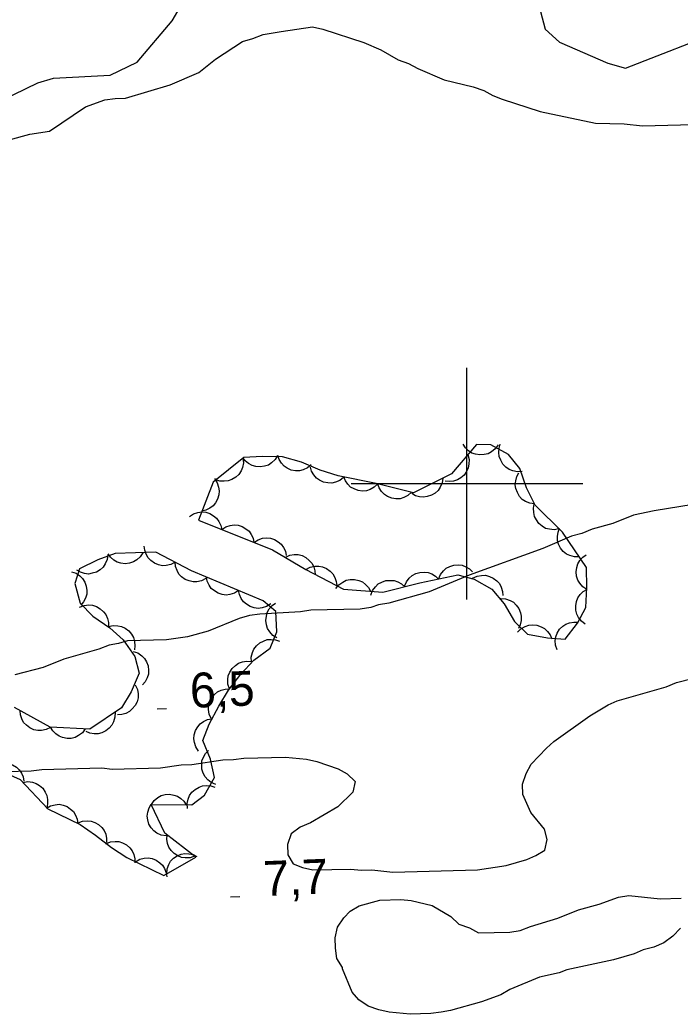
# Model space of a CAD drawing. Extents: x 336540 to 340074, y 5572036 to 5573747.
# Drawn here: x 337361.4 to 337418.4, y 5572954.2 to 5573040 of the extents above; entities that cross this region are included whole.
import ezdxf

# ---------------------------------------------------------------- set-up
doc = ezdxf.new("R2010")
doc.units = 0
for name, color, linetype in [('Niveau 2', 7, 'Continuous'), ('Niveau 3', 7, 'Continuous'), ('Niveau 44', 7, 'Continuous'), ('Niveau 61', 7, 'Continuous')]:
    doc.layers.add(name, color=color, linetype=linetype)

msp = doc.modelspace()

# ---------------------------------------------------------------- linework, layer by layer
at = {"layer": 'Niveau 2'}
for points in [[(337311.92, 5573027.2), (337321.42, 5573026.84), (337323.62, 5573026.6), (337325.18, 5573025.85), (337328.23, 5573022.94), (337330.16, 5573021.51), (337331.52, 5573021.09), (337334.91, 5573021.09), (337337.1, 5573021.71), (337339.82, 5573024.41), (337343.42, 5573026.96), (337351.15, 5573031.07), (337354.47, 5573032.27), (337359.85, 5573033.05), (337362.98, 5573034.59), (337364.33, 5573034.99), (337369.22, 5573035.24), (337371.54, 5573036.37), (337374.57, 5573039.93), (337377.21, 5573044.47)], [(337406.35, 5573040.72), (337406.74, 5573039.21), (337407.99, 5573038.09), (337412.15, 5573036.27), (337413.69, 5573035.83), (337422.39, 5573039.25), (337426.4, 5573040.99)], [(337360.5, 5573029.65), (337362.29, 5573030.14), (337363.98, 5573030.4), (337367.09, 5573032.5), (337368.76, 5573033.1), (337369.66, 5573033.23), (337370.56, 5573033.25), (337374.41, 5573034.4), (337376.86, 5573035.47), (337378.3, 5573036.63), (337380.63, 5573038.15), (337381.52, 5573038.4), (337382.41, 5573038.76), (337383.98, 5573039.02), (337386.68, 5573039.42), (337387.58, 5573039.22), (337391.1, 5573038.06), (337392.58, 5573037.42), (337394.06, 5573036.56), (337394.97, 5573036.24), (337395.77, 5573035.81), (337398.05, 5573034.85), (337400.54, 5573034.23), (337401.45, 5573033.92), (337402.24, 5573033.48), (337403.04, 5573033.17), (337406.33, 5573032.12), (337411.08, 5573031.1), (337413.56, 5573031.05), (337415.14, 5573030.86), (337419.53, 5573030.97)], [(337419.52, 5572998.19), (337416.16, 5572997.66), (337414.37, 5572997.28), (337412.58, 5572996.56), (337410.79, 5572996.07), (337409.9, 5572995.71), (337409.01, 5572995.46), (337406.55, 5572994.39), (337400.19, 5572992.1), (337396.74, 5572990.67), (337393.27, 5572989.68), (337392.37, 5572989.55), (337391.7, 5572989.31), (337390.8, 5572989.17), (337386.53, 5572989.07), (337385.63, 5572988.94), (337382.14, 5572988.74), (337381.25, 5572988.61), (337380.35, 5572988.36), (337377.67, 5572987.28), (337375.88, 5572986.79), (337374.09, 5572986.52), (337370.71, 5572986.44), (337369.93, 5572986.2)], [(337369.93, 5572986.2), (337369.15, 5572986.07), (337368.25, 5572985.71), (337365.23, 5572984.85), (337363.45, 5572984.13), (337360.99, 5572983.51)], [(337412.95, 5572981.26), (337417.2, 5572982.48), (337418.09, 5572982.84), (337421, 5572983.59)], [(337359.05, 5572975.13), (337362.42, 5572975.21), (337363.32, 5572975.34), (337368.5, 5572975.47), (337369.4, 5572975.37), (337373.57, 5572975.47), (337375.36, 5572975.74), (337376.26, 5572975.76), (337378.95, 5572976.17), (337379.85, 5572976.19), (337380.75, 5572976.32), (337384.35, 5572976.41), (337386.16, 5572976.22), (337387.06, 5572976.02), (337388.88, 5572975.39), (337389.68, 5572974.96), (337390.37, 5572974.3), (337390.17, 5572973.39), (337388.85, 5572972.12), (337386.51, 5572970.72), (337385.62, 5572970.36), (337384.85, 5572969.77), (337384.53, 5572968.87), (337384.55, 5572967.97), (337385.02, 5572967.19), (337385.82, 5572966.87), (337386.72, 5572966.67), (337389.99, 5572966.74), (337390.89, 5572966.65), (337391.79, 5572966.67), (337393.6, 5572966.49), (337400.91, 5572966.67), (337403.38, 5572967.06), (337405.17, 5572967.56), (337405.95, 5572967.91), (337406.72, 5572968.38), (337406.93, 5572969.29), (337406.68, 5572970.18), (337405.52, 5572971.62), (337404.81, 5572973.18), (337404.79, 5572974.08), (337405.1, 5572974.99), (337405.53, 5572975.79), (337406.85, 5572977.17), (337407.51, 5572977.75), (337410.61, 5572979.96), (337412.17, 5572980.9), (337412.95, 5572981.26)], [(337389.26, 5572958.14), (337389.26, 5572958.25), (337388.79, 5572959.03), (337388.66, 5572959.92), (337388.64, 5572960.82), (337388.84, 5572961.73), (337389.38, 5572962.53), (337389.93, 5572963.11), (337390.71, 5572963.57), (337392.5, 5572964.07), (337394.3, 5572964.11), (337395.2, 5572964.02), (337397.01, 5572963.61), (337398.61, 5572962.64), (337399.3, 5572961.98), (337400.21, 5572961.66), (337401, 5572961.23), (337403.7, 5572961.3), (337404.6, 5572961.43), (337405.49, 5572961.79), (337407.83, 5572962.52), (337409.62, 5572963.24), (337411.41, 5572963.73), (337413.08, 5572964.33), (337413.98, 5572964.47), (337416.68, 5572964.19), (337418.48, 5572964.24)], [(337418.43, 5572961.65), (337417.77, 5572960.96), (337417, 5572960.38), (337416.11, 5572960.02), (337415.21, 5572959.77), (337414.43, 5572959.42), (337412.65, 5572958.92), (337408.62, 5572958.04), (337407.95, 5572957.8), (337406.27, 5572957.42), (337403.71, 5572956.35), (337402.93, 5572955.88), (337401.26, 5572955.28), (337398.58, 5572954.54), (337397.79, 5572954.4), (337396.89, 5572954.27), (337395.1, 5572954.23), (337393.29, 5572954.41), (337392.39, 5572954.61), (337391.48, 5572954.93), (337390.68, 5572955.47), (337390.1, 5572956.13), (337389.26, 5572958.14)]]:
    msp.add_lwpolyline(points, dxfattribs=at)
at = {"layer": 'Niveau 3'}
for p, q in [((337373.28, 5572980.58), (337374.08, 5572980.61)), ((337379.61, 5572964.34), (337380.41, 5572964.38))]:
    msp.add_line(p, q, dxfattribs=at)
at = {"layer": 'Niveau 44'}
for points in [[(337386.11, 5572992.59), (337389.35, 5572990.9), (337392.74, 5572990.64), (337395.95, 5572991.43), (337399.21, 5572992.12), (337400.63, 5572991.75), (337402.14, 5572990.89), (337403.2, 5572989.62), (337404.09, 5572988.1), (337405.23, 5572987.02), (337406.95, 5572986.69), (337408.47, 5572986.58), (337409.53, 5572987.97), (337410.27, 5572989.3), (337410.35, 5572991.05), (337410.31, 5572992.76), (337408.23, 5572995.8), (337405.89, 5572998.15), (337405.13, 5572999.65), (337404.56, 5573001.31), (337403.6, 5573002.5), (337402.07, 5573003.35), (337400.83, 5573003.37), (337398.66, 5573000.85), (337395.38, 5572999.21), (337392.16, 5573000), (337388.9, 5573000.68), (337387.34, 5573001.16), (337385.73, 5573001.85), (337384.09, 5573002.31), (337382.34, 5573002.35), (337380.74, 5573002.26), (337378.1, 5573000.13), (337376.83, 5572996.86), (337383.23, 5572994.28), (337386.11, 5572992.59)], [(337402.68, 5573003.34), (337402.44, 5573003), (337402.12, 5573002.75), (337401.83, 5573002.58), (337401.49, 5573002.5), (337401.12, 5573002.47), (337400.75, 5573002.54), (337400.43, 5573002.63), (337400.14, 5573002.83), (337399.87, 5573003.09), (337399.68, 5573003.39)], [(337404.77, 5573001.06), (337404.35, 5573001.02), (337403.95, 5573001.11), (337403.64, 5573001.22), (337403.36, 5573001.42), (337403.1, 5573001.69), (337402.91, 5573002.03), (337402.79, 5573002.33), (337402.75, 5573002.68), (337402.78, 5573003.05), (337402.88, 5573003.39)], [(337383.66, 5573002.42), (337383.45, 5573002.07), (337383.15, 5573001.79), (337382.87, 5573001.6), (337382.54, 5573001.5), (337382.17, 5573001.44), (337381.79, 5573001.49), (337381.47, 5573001.56), (337381.17, 5573001.73), (337380.88, 5573001.97), (337380.67, 5573002.26)], [(337386.57, 5573001.62), (337386.25, 5573001.35), (337385.87, 5573001.18), (337385.56, 5573001.09), (337385.21, 5573001.1), (337384.84, 5573001.17), (337384.5, 5573001.33), (337384.22, 5573001.5), (337383.99, 5573001.77), (337383.79, 5573002.08), (337383.68, 5573002.43)], [(337400.08, 5573002.5), (337400.19, 5573002.09), (337400.17, 5573001.69), (337400.12, 5573001.36), (337399.97, 5573001.04), (337399.75, 5573000.74), (337399.46, 5573000.5), (337399.18, 5573000.32), (337398.85, 5573000.22), (337398.48, 5573000.18), (337398.12, 5573000.22)], [(337380.68, 5573002.21), (337380.72, 5573001.8), (337380.63, 5573001.4), (337380.52, 5573001.09), (337380.31, 5573000.8), (337380.05, 5573000.55), (337379.71, 5573000.36), (337379.41, 5573000.23), (337379.06, 5573000.2), (337378.69, 5573000.22), (337378.35, 5573000.33)], [(337389.36, 5573000.54), (337389.04, 5573000.28), (337388.66, 5573000.12), (337388.34, 5573000.04), (337387.99, 5573000.06), (337387.63, 5573000.13), (337387.29, 5573000.31), (337387.01, 5573000.48), (337386.79, 5573000.75), (337386.6, 5573001.08), (337386.5, 5573001.42)], [(337392.31, 5572999.97), (337392.01, 5572999.68), (337391.65, 5572999.49), (337391.34, 5572999.38), (337390.99, 5572999.36), (337390.62, 5572999.41), (337390.26, 5572999.55), (337389.97, 5572999.7), (337389.73, 5572999.95), (337389.51, 5573000.25), (337389.38, 5573000.58)], [(337405.84, 5572998.25), (337405.43, 5572998.3), (337405.06, 5572998.47), (337404.77, 5572998.64), (337404.54, 5572998.9), (337404.35, 5572999.22), (337404.23, 5572999.58), (337404.17, 5572999.9), (337404.21, 5573000.25), (337404.31, 5573000.61), (337404.48, 5573000.92)], [(337378.21, 5573000.43), (337378.45, 5573000.08), (337378.58, 5572999.7), (337378.64, 5572999.37), (337378.6, 5572999.02), (337378.49, 5572998.67), (337378.3, 5572998.34), (337378.1, 5572998.08), (337377.81, 5572997.87), (337377.48, 5572997.71), (337377.13, 5572997.63)], [(337395.22, 5572999.25), (337394.91, 5572998.97), (337394.55, 5572998.79), (337394.23, 5572998.69), (337393.88, 5572998.69), (337393.52, 5572998.74), (337393.16, 5572998.9), (337392.88, 5572999.06), (337392.64, 5572999.32), (337392.44, 5572999.63), (337392.31, 5572999.96)], [(337397.92, 5573000.48), (337397.87, 5573000.07), (337397.7, 5572999.7), (337397.52, 5572999.42), (337397.26, 5572999.18), (337396.94, 5572998.99), (337396.58, 5572998.88), (337396.26, 5572998.82), (337395.91, 5572998.86), (337395.55, 5572998.96), (337395.24, 5572999.14)], [(337407.93, 5572996.1), (337407.52, 5572996.02), (337407.12, 5572996.07), (337406.79, 5572996.14), (337406.49, 5572996.32), (337406.21, 5572996.56), (337405.99, 5572996.87), (337405.83, 5572997.16), (337405.76, 5572997.5), (337405.74, 5572997.87), (337405.81, 5572998.23)], [(337376.06, 5572997.17), (337376.41, 5572997.4), (337376.8, 5572997.52), (337377.13, 5572997.58), (337377.47, 5572997.53), (337377.83, 5572997.42), (337378.15, 5572997.22), (337378.41, 5572997.02), (337378.61, 5572996.73), (337378.77, 5572996.4), (337378.85, 5572996.05)], [(337378.85, 5572996.05), (337379.19, 5572996.28), (337379.58, 5572996.4), (337379.91, 5572996.45), (337380.26, 5572996.41), (337380.61, 5572996.3), (337380.94, 5572996.1), (337381.2, 5572995.9), (337381.4, 5572995.61), (337381.55, 5572995.28), (337381.63, 5572994.93)], [(337409.68, 5572993.68), (337409.27, 5572993.67), (337408.88, 5572993.79), (337408.58, 5572993.92), (337408.31, 5572994.15), (337408.07, 5572994.44), (337407.91, 5572994.79), (337407.81, 5572995.1), (337407.8, 5572995.45), (337407.86, 5572995.82), (337407.99, 5572996.15)], [(337374.82, 5572993.21), (337374.45, 5572993.02), (337374.06, 5572992.94), (337373.73, 5572992.91), (337373.38, 5572992.99), (337373.04, 5572993.13), (337372.74, 5572993.37), (337372.5, 5572993.59), (337372.33, 5572993.9), (337372.21, 5572994.25), (337372.17, 5572994.61)], [(337381.63, 5572994.93), (337381.98, 5572995.16), (337382.36, 5572995.28), (337382.69, 5572995.33), (337383.04, 5572995.29), (337383.39, 5572995.18), (337383.72, 5572994.98), (337383.98, 5572994.78), (337384.18, 5572994.49), (337384.34, 5572994.16), (337384.41, 5572993.8)], [(337358.29, 5572975.88), (337361.47, 5572974.47), (337363.84, 5572971.94), (337366.64, 5572970.59), (337367.97, 5572969.68), (337369.35, 5572968.6), (337370.67, 5572967.73), (337373.85, 5572966.2), (337376.6, 5572967.77), (337373.93, 5572969.84), (337372.77, 5572972.32), (337376.28, 5572972.28), (337377.36, 5572973.12), (337378.21, 5572974.65), (337377.87, 5572976.22), (337377.21, 5572977.84), (337377.77, 5572979.25), (337378.59, 5572980.8), (337379.43, 5572982.18), (337380.5, 5572983.56), (337381.62, 5572984.76), (337383.02, 5572985.8), (337383.59, 5572987.22), (337383.51, 5572988.97), (337382.42, 5572989.89), (337376.24, 5572992.47), (337373.17, 5572994.08), (337369.66, 5572993.96), (337368.16, 5572993.43), (337366.59, 5572992.65), (337366.17, 5572991.38), (337366.64, 5572989.7), (337367.73, 5572988.56), (337369.18, 5572987.57), (337370.35, 5572986.52), (337371.34, 5572985.08), (337371.73, 5572983.65), (337371.04, 5572982.04), (337370.21, 5572980.65), (337367.46, 5572978.81), (337364.06, 5572978.98), (337360.97, 5572980.67)], [(337369.03, 5572993.86), (337368.97, 5572993.45), (337368.8, 5572993.08), (337368.63, 5572992.8), (337368.36, 5572992.57), (337368.05, 5572992.37), (337367.68, 5572992.26), (337367.36, 5572992.2), (337367.01, 5572992.24), (337366.65, 5572992.35), (337366.34, 5572992.53)], [(337372.04, 5572994.04), (337371.82, 5572993.69), (337371.51, 5572993.42), (337371.23, 5572993.24), (337370.9, 5572993.14), (337370.53, 5572993.09), (337370.15, 5572993.14), (337369.83, 5572993.22), (337369.53, 5572993.41), (337369.25, 5572993.65), (337369.04, 5572993.94)], [(337384.33, 5572993.64), (337384.71, 5572993.82), (337385.11, 5572993.88), (337385.44, 5572993.88), (337385.78, 5572993.79), (337386.11, 5572993.63), (337386.4, 5572993.38), (337386.63, 5572993.15), (337386.79, 5572992.83), (337386.89, 5572992.48), (337386.92, 5572992.12)], [(337410.35, 5572990.87), (337410, 5572991.1), (337409.74, 5572991.41), (337409.56, 5572991.68), (337409.46, 5572992.02), (337409.42, 5572992.39), (337409.48, 5572992.77), (337409.56, 5572993.08), (337409.75, 5572993.38), (337409.99, 5572993.66), (337410.28, 5572993.87)], [(337377.48, 5572991.82), (337377.11, 5572991.62), (337376.71, 5572991.54), (337376.38, 5572991.52), (337376.04, 5572991.6), (337375.7, 5572991.74), (337375.39, 5572991.97), (337375.16, 5572992.2), (337374.99, 5572992.51), (337374.86, 5572992.86), (337374.82, 5572993.21)], [(337386.11, 5572992.59), (337386.48, 5572992.79), (337386.88, 5572992.87), (337387.21, 5572992.89), (337387.55, 5572992.81), (337387.89, 5572992.67), (337388.2, 5572992.44), (337388.43, 5572992.22), (337388.6, 5572991.91), (337388.73, 5572991.56), (337388.77, 5572991.2)], [(337397.55, 5572991.77), (337397.71, 5572992.16), (337397.97, 5572992.47), (337398.21, 5572992.7), (337398.52, 5572992.86), (337398.88, 5572992.97), (337399.26, 5572992.98), (337399.58, 5572992.96), (337399.91, 5572992.83), (337400.23, 5572992.64), (337400.49, 5572992.39)], [(337365.88, 5572992.4), (337366.28, 5572992.27), (337366.61, 5572992.03), (337366.85, 5572991.81), (337367.03, 5572991.5), (337367.16, 5572991.16), (337367.2, 5572990.78), (337367.2, 5572990.45), (337367.09, 5572990.12), (337366.93, 5572989.79), (337366.69, 5572989.51)], [(337380.3, 5572990.77), (337379.95, 5572990.55), (337379.56, 5572990.43), (337379.23, 5572990.38), (337378.89, 5572990.43), (337378.53, 5572990.54), (337378.21, 5572990.75), (337377.95, 5572990.95), (337377.76, 5572991.24), (337377.6, 5572991.58), (337377.53, 5572991.93)], [(337394.62, 5572991.15), (337394.78, 5572991.54), (337395.03, 5572991.85), (337395.27, 5572992.08), (337395.59, 5572992.24), (337395.94, 5572992.34), (337396.32, 5572992.36), (337396.65, 5572992.34), (337396.98, 5572992.21), (337397.3, 5572992.02), (337397.55, 5572991.77)], [(337400.49, 5572991.83), (337400.87, 5572992.01), (337401.27, 5572992.08), (337401.6, 5572992.09), (337401.94, 5572992), (337402.27, 5572991.85), (337402.57, 5572991.6), (337402.8, 5572991.37), (337402.96, 5572991.06), (337403.07, 5572990.7), (337403.1, 5572990.34)], [(337388.7, 5572990.95), (337388.96, 5572991.28), (337389.29, 5572991.51), (337389.59, 5572991.66), (337389.93, 5572991.72), (337390.3, 5572991.73), (337390.67, 5572991.63), (337390.98, 5572991.52), (337391.26, 5572991.31), (337391.51, 5572991.03), (337391.69, 5572990.72)], [(337391.72, 5572990.39), (337391.86, 5572990.78), (337392.11, 5572991.1), (337392.34, 5572991.34), (337392.65, 5572991.51), (337393, 5572991.63), (337393.38, 5572991.65), (337393.71, 5572991.64), (337394.04, 5572991.53), (337394.36, 5572991.35), (337394.63, 5572991.1)], [(337383.07, 5572989.62), (337382.72, 5572989.39), (337382.33, 5572989.28), (337382, 5572989.23), (337381.65, 5572989.27), (337381.3, 5572989.39), (337380.98, 5572989.59), (337380.72, 5572989.79), (337380.53, 5572990.08), (337380.37, 5572990.42), (337380.3, 5572990.77)], [(337410.2, 5572987.87), (337409.87, 5572988.12), (337409.63, 5572988.45), (337409.47, 5572988.74), (337409.4, 5572989.08), (337409.38, 5572989.45), (337409.46, 5572989.83), (337409.56, 5572990.14), (337409.77, 5572990.42), (337410.03, 5572990.68), (337410.34, 5572990.87)], [(337366.59, 5572989.34), (337366.98, 5572989.49), (337367.38, 5572989.53), (337367.71, 5572989.51), (337368.04, 5572989.39), (337368.37, 5572989.21), (337368.64, 5572988.94), (337368.85, 5572988.7), (337368.99, 5572988.37), (337369.07, 5572988.01), (337369.07, 5572987.65)], [(337383.61, 5572986.7), (337383.26, 5572986.91), (337382.99, 5572987.22), (337382.8, 5572987.49), (337382.7, 5572987.83), (337382.65, 5572988.19), (337382.7, 5572988.57), (337382.77, 5572988.89), (337382.95, 5572989.19), (337383.19, 5572989.48), (337383.48, 5572989.69)], [(337402.92, 5572990.1), (337403.34, 5572990.07), (337403.72, 5572989.93), (337404.01, 5572989.77), (337404.26, 5572989.52), (337404.47, 5572989.22), (337404.61, 5572988.86), (337404.69, 5572988.55), (337404.67, 5572988.19), (337404.59, 5572987.83), (337404.44, 5572987.51)], [(337369.08, 5572987.66), (337369.48, 5572987.76), (337369.89, 5572987.74), (337370.21, 5572987.68), (337370.53, 5572987.52), (337370.82, 5572987.3), (337371.06, 5572987), (337371.24, 5572986.72), (337371.32, 5572986.38), (337371.36, 5572986.01), (337371.31, 5572985.66)], [(337404.36, 5572987.19), (337404.66, 5572987.48), (337405.02, 5572987.67), (337405.33, 5572987.79), (337405.68, 5572987.81), (337406.04, 5572987.78), (337406.4, 5572987.64), (337406.69, 5572987.5), (337406.95, 5572987.25), (337407.17, 5572986.95), (337407.31, 5572986.62)], [(337407.77, 5572985.66), (337407.63, 5572986.05), (337407.62, 5572986.46), (337407.66, 5572986.79), (337407.79, 5572987.11), (337407.99, 5572987.43), (337408.27, 5572987.69), (337408.53, 5572987.88), (337408.86, 5572988), (337409.23, 5572988.06), (337409.59, 5572988.04)], [(337381.42, 5572984.61), (337381.4, 5572985.03), (337381.5, 5572985.42), (337381.63, 5572985.73), (337381.84, 5572986), (337382.12, 5572986.25), (337382.46, 5572986.42), (337382.77, 5572986.54), (337383.12, 5572986.56), (337383.49, 5572986.52), (337383.83, 5572986.4)], [(337371.22, 5572985.52), (337371.62, 5572985.39), (337371.95, 5572985.15), (337372.19, 5572984.92), (337372.36, 5572984.62), (337372.49, 5572984.27), (337372.53, 5572983.89), (337372.52, 5572983.56), (337372.41, 5572983.23), (337372.24, 5572982.9), (337372.01, 5572982.63)], [(337379.51, 5572982.29), (337379.38, 5572982.69), (337379.38, 5572983.09), (337379.41, 5572983.42), (337379.55, 5572983.74), (337379.75, 5572984.05), (337380.03, 5572984.31), (337380.29, 5572984.51), (337380.63, 5572984.62), (337380.99, 5572984.68), (337381.35, 5572984.66)], [(337371.39, 5572982.63), (337371.57, 5572982.25), (337371.63, 5572981.85), (337371.63, 5572981.52), (337371.54, 5572981.18), (337371.37, 5572980.85), (337371.13, 5572980.56), (337370.89, 5572980.34), (337370.57, 5572980.18), (337370.22, 5572980.08), (337369.86, 5572980.06)], [(337377.94, 5572979.73), (337377.77, 5572980.11), (337377.71, 5572980.52), (337377.71, 5572980.85), (337377.81, 5572981.18), (337377.98, 5572981.52), (337378.23, 5572981.81), (337378.47, 5572982.03), (337378.79, 5572982.18), (337379.14, 5572982.28), (337379.5, 5572982.3)], [(337364.08, 5572978.97), (337363.71, 5572978.78), (337363.31, 5572978.7), (337362.98, 5572978.69), (337362.64, 5572978.77), (337362.3, 5572978.92), (337362, 5572979.16), (337361.76, 5572979.39), (337361.6, 5572979.7), (337361.48, 5572980.05), (337361.45, 5572980.41)], [(337369.64, 5572980.27), (337369.63, 5572979.85), (337369.51, 5572979.46), (337369.38, 5572979.16), (337369.14, 5572978.9), (337368.85, 5572978.67), (337368.51, 5572978.51), (337368.2, 5572978.41), (337367.84, 5572978.4), (337367.48, 5572978.46), (337367.14, 5572978.6)], [(337376.85, 5572976.93), (337376.61, 5572977.28), (337376.49, 5572977.67), (337376.44, 5572977.99), (337376.48, 5572978.34), (337376.59, 5572978.69), (337376.78, 5572979.02), (337376.98, 5572979.28), (337377.27, 5572979.48), (337377.61, 5572979.64), (337377.96, 5572979.72)], [(337367.08, 5572978.83), (337366.83, 5572978.5), (337366.5, 5572978.26), (337366.21, 5572978.1), (337365.87, 5572978.02), (337365.5, 5572978.01), (337365.12, 5572978.09), (337364.81, 5572978.2), (337364.53, 5572978.41), (337364.27, 5572978.67), (337364.08, 5572978.98)], [(337378.34, 5572974.04), (337377.95, 5572974.2), (337377.64, 5572974.45), (337377.41, 5572974.69), (337377.25, 5572975.01), (337377.14, 5572975.36), (337377.12, 5572975.74), (337377.14, 5572976.07), (337377.27, 5572976.4), (337377.46, 5572976.71), (337377.71, 5572976.98)], [(337359.04, 5572975.55), (337359.39, 5572975.77), (337359.78, 5572975.88), (337360.11, 5572975.92), (337360.46, 5572975.86), (337360.81, 5572975.74), (337361.13, 5572975.53), (337361.38, 5572975.32), (337361.57, 5572975.03), (337361.72, 5572974.69), (337361.78, 5572974.33)], [(337361.7, 5572974.22), (337362.11, 5572974.29), (337362.52, 5572974.23), (337362.84, 5572974.14), (337363.13, 5572973.96), (337363.41, 5572973.71), (337363.62, 5572973.39), (337363.77, 5572973.1), (337363.83, 5572972.75), (337363.83, 5572972.38), (337363.75, 5572972.03)], [(337375.88, 5572971.97), (337375.86, 5572972.39), (337375.95, 5572972.78), (337376.06, 5572973.09), (337376.28, 5572973.37), (337376.55, 5572973.62), (337376.89, 5572973.81), (337377.19, 5572973.93), (337377.54, 5572973.96), (337377.91, 5572973.92), (337378.25, 5572973.81)], [(337372.78, 5572972.32), (337373.02, 5572972.66), (337373.33, 5572972.92), (337373.62, 5572973.08), (337373.96, 5572973.17), (337374.33, 5572973.2), (337374.71, 5572973.13), (337375.02, 5572973.04), (337375.31, 5572972.84), (337375.58, 5572972.59), (337375.78, 5572972.29)], [(337363.73, 5572972), (337364.09, 5572972.21), (337364.48, 5572972.3), (337364.81, 5572972.33), (337365.16, 5572972.26), (337365.5, 5572972.13), (337365.81, 5572971.91), (337366.06, 5572971.7), (337366.24, 5572971.39), (337366.38, 5572971.05), (337366.43, 5572970.69)], [(337374.04, 5572969.61), (337373.63, 5572969.67), (337373.26, 5572969.85), (337372.98, 5572970.04), (337372.76, 5572970.31), (337372.57, 5572970.62), (337372.47, 5572970.99), (337372.42, 5572971.32), (337372.47, 5572971.66), (337372.58, 5572972.02), (337372.77, 5572972.33)], [(337366.45, 5572970.72), (337366.83, 5572970.88), (337367.24, 5572970.91), (337367.57, 5572970.89), (337367.9, 5572970.77), (337368.22, 5572970.59), (337368.5, 5572970.33), (337368.71, 5572970.08), (337368.84, 5572969.75), (337368.92, 5572969.39), (337368.92, 5572969.03)], [(337376.5, 5572967.85), (337376.11, 5572967.72), (337375.7, 5572967.71), (337375.37, 5572967.74), (337375.05, 5572967.88), (337374.74, 5572968.08), (337374.48, 5572968.36), (337374.28, 5572968.63), (337374.17, 5572968.96), (337374.11, 5572969.32), (337374.13, 5572969.68)], [(337368.85, 5572968.93), (337369.24, 5572969.09), (337369.64, 5572969.13), (337369.97, 5572969.12), (337370.3, 5572969.01), (337370.63, 5572968.83), (337370.91, 5572968.57), (337371.12, 5572968.32), (337371.26, 5572968), (337371.35, 5572967.64), (337371.35, 5572967.28)], [(337374.1, 5572966.34), (337374.13, 5572966.76), (337374.28, 5572967.14), (337374.44, 5572967.43), (337374.69, 5572967.68), (337375, 5572967.89), (337375.36, 5572968.02), (337375.67, 5572968.1), (337376.02, 5572968.07), (337376.38, 5572967.99), (337376.71, 5572967.83)], [(337371.41, 5572967.37), (337371.77, 5572967.59), (337372.17, 5572967.68), (337372.49, 5572967.71), (337372.84, 5572967.65), (337373.18, 5572967.51), (337373.5, 5572967.29), (337373.74, 5572967.08), (337373.92, 5572966.78), (337374.06, 5572966.43), (337374.11, 5572966.07)]]:
    msp.add_lwpolyline(points, dxfattribs=at)
at = {"layer": 'Niveau 61'}
for points in [[(337400, 5572990), (337400, 5573010)], [(337390, 5573000), (337410, 5573000)]]:
    msp.add_lwpolyline(points, dxfattribs=at)

# ---------------------------------------------------------------- texts
at = {"layer": 'Niveau 3'}
for s, p in [('6,5    ', (337376.16, 5572980.65)), ('7,7    ', (337382.49, 5572964.42))]:
    msp.add_text(s, height=2.9999, rotation=2.27627, dxfattribs=at).set_placement(p)

doc.saveas('drawing.dxf')
